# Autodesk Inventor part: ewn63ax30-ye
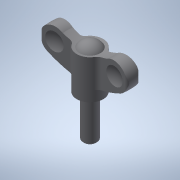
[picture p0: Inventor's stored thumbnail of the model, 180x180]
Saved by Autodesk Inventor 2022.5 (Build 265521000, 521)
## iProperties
Created: 2017-05
Part Number: ewn63ax30-ye
Material: 一般
Document SubType Name: Modeling
Designer: imaocorp
Density: 1 g/cm^3
Appearance: 既定
Author: imaocorp
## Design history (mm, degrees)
node "ewn63ax30-ye.x_t1"
node "ewn63ax30-ye"
node "Base1"
